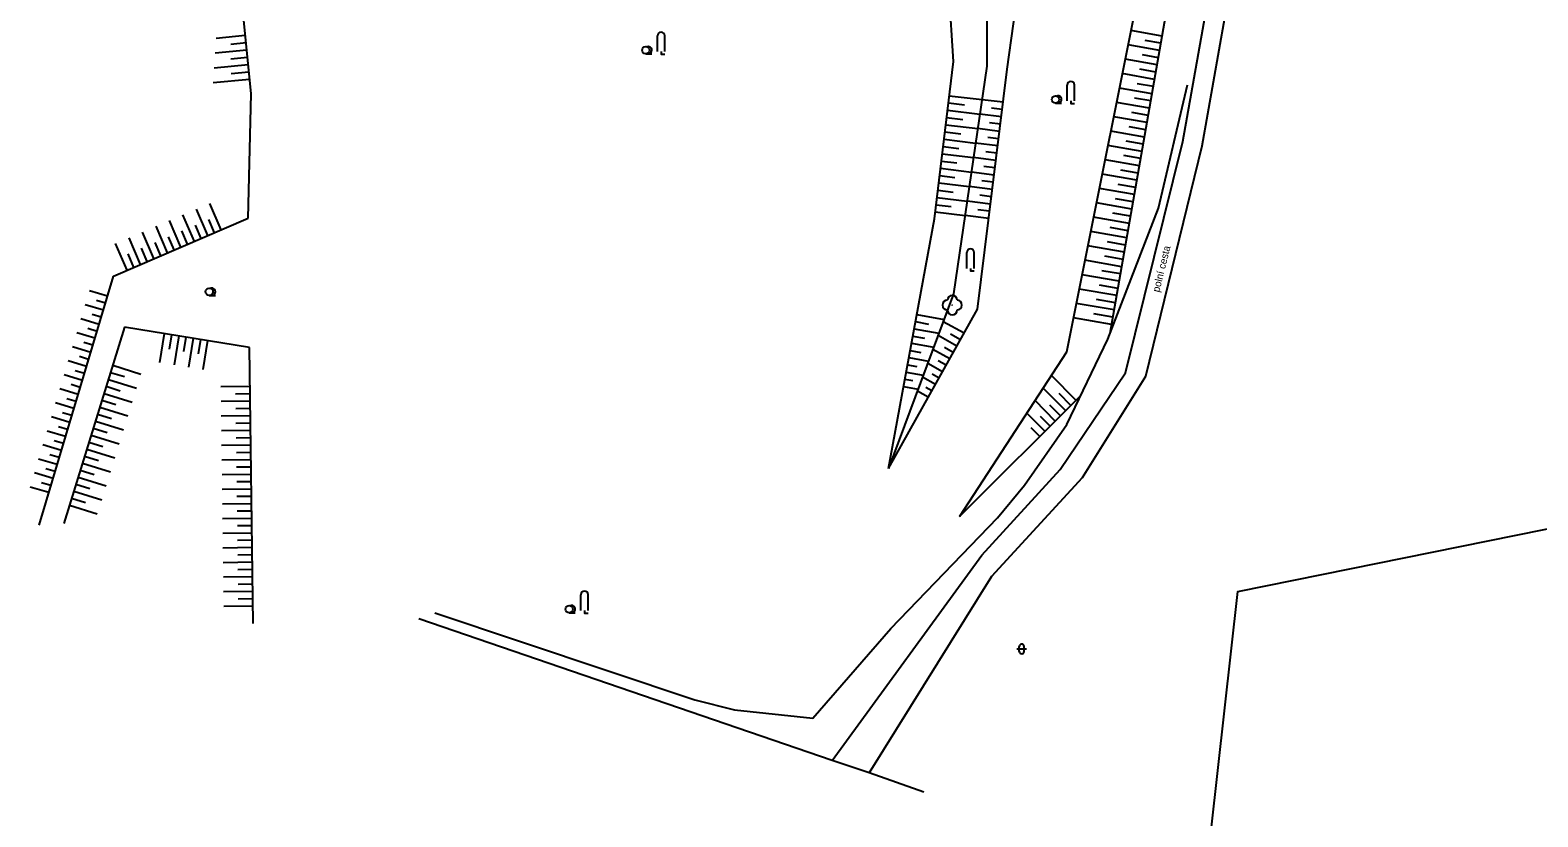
# Model space of a CAD drawing. Extents: x -737488 to -734267, y -1145775 to -1142573.
# Drawn here: x -735052.3 to -734897.8, y -1143083.7 to -1143003.1 of the extents above; entities that cross this region are included whole.
import ezdxf

# ---------------------------------------------------------------- set-up
doc = ezdxf.new("R2010")
doc.units = 0
for name, color, linetype in [('Vrstva 1', 7, 'Continuous'), ('Vrstva 10', 7, 'Continuous'), ('Vrstva 11', 7, 'Continuous'), ('Vrstva 12', 7, 'Continuous'), ('Vrstva 14', 7, 'Continuous'), ('Vrstva 3', 7, 'Continuous'), ('Vrstva 9', 7, 'Continuous')]:
    doc.layers.add(name, color=color, linetype=linetype)

# ---------------------------------------------------------------- blocks, each defined once
blk = doc.blocks.new('3.130')
at = {"layer": 'Vrstva 1'}
blk.add_circle((0, 0), 0.001, dxfattribs=at)
for centre, start, end in [((-1, 0), 90, 270), ((0, 1), 0, 180), ((1, 0), 270, 90), ((0, -1), 180, 360)]:
    blk.add_arc(centre, 1, start, end, dxfattribs=at)
blk = doc.blocks.new('3.100')
at = {"layer": 'Vrstva 1'}
for p, q in [((-0.75, 0), (-0.75, 3.25)), ((0.75, 0), (0.75, 3.25))]:
    blk.add_line(p, q, dxfattribs=at)
blk.add_lwpolyline([(0, 0), (0, -0.5), (0.75, -0.5)], dxfattribs=at)
blk.add_arc((0, 3.25), 0.75, 0, 180, dxfattribs=at)
blk = doc.blocks.new('3.110')
at = {"layer": 'Vrstva 1'}
blk.add_line((0, -0.75), (1.25, -0.75), dxfattribs=at)
blk.add_circle((0, 0), 0.75, dxfattribs=at)
blk.add_arc((0.5, 0), 0.75, 249.4944, 109.0474, dxfattribs=at)
blk = doc.blocks.new('3.160')
at = {"layer": 'Vrstva 1'}
for p, q in [((-1, 0), (1, 0)), ((-0.5, -0.5), (-0.5, 0.5)), ((0.5, -0.5), (0.5, 0.5))]:
    blk.add_line(p, q, dxfattribs=at)
for centre, start, end in [((0, 0.5), 0, 180), ((0, -0.5), 180, 360)]:
    blk.add_arc(centre, 0.5, start, end, dxfattribs=at)

msp = doc.modelspace()

# ---------------------------------------------------------------- linework, layer by layer
at = {"layer": 'Vrstva 10'}
for points in [[(-734934.2, -1143014.49), (-734928.93, -1142984.91)], [(-734927.04, -1142985.42), (-734932.25, -1143014.98)], [(-734940.09, -1143038.19), (-734934.2, -1143014.49)], [(-734932.25, -1143014.98), (-734938.02, -1143038.56)], [(-734946.76, -1143048.08), (-734940.09, -1143038.19)], [(-734938.02, -1143038.56), (-734944.5, -1143048.94)], [(-734954.79, -1143056.87), (-734946.76, -1143048.08)], [(-734944.5, -1143048.94), (-734953.81, -1143059.04)], [(-734970.13, -1143077.9), (-734954.79, -1143056.87)], [(-734953.81, -1143059.04), (-734966.34, -1143079.17)]]:
    msp.add_lwpolyline(points, dxfattribs=at)
at = {"layer": 'Vrstva 11'}
msp.add_lwpolyline([(-734932.65, -1143097.27), (-734928.56, -1143060.61), (-734817.4, -1143038.1), (-734801.73, -1143030.15)], dxfattribs=at)
at = {"layer": 'Vrstva 12'}
for points in [[(-734937.19, -1142991.51), (-734946.11, -1143036.08)], [(-734941.65, -1143034.14), (-734934.15, -1142991.37)], [(-734957.7, -1143006.28), (-734958.58, -1142992.32)], [(-734954.25, -1142992.81), (-734954.27, -1143006.77)], [(-734952.18, -1143007.07), (-734950.26, -1142993.11)], [(-735029.64, -1143009.61), (-735030.82, -1142997.59)], [(-735030.23, -1143003.64), (-735033.21, -1143003.93)], [(-735030.15, -1143004.39), (-735031.71, -1143004.54)], [(-734936.31, -1143003.68), (-734939.51, -1143003.12)], [(-734936.44, -1143004.42), (-734938.05, -1143004.14)], [(-735030.08, -1143005.13), (-735033.31, -1143005.45)], [(-735030.01, -1143005.88), (-735031.69, -1143006.04)], [(-734936.57, -1143005.16), (-734939.81, -1143004.59)], [(-734936.7, -1143005.9), (-734938.33, -1143005.61)], [(-735029.93, -1143006.62), (-735033.41, -1143006.97)], [(-735029.86, -1143007.37), (-735031.66, -1143007.55)], [(-734959.65, -1143022.42), (-734957.7, -1143006.28)], [(-734954.27, -1143006.77), (-734957.68, -1143030.1)], [(-734955.24, -1143031.68), (-734952.18, -1143007.07)], [(-734937.09, -1143008.12), (-734940.4, -1143007.53)], [(-734936.83, -1143006.64), (-734940.1, -1143006.06)], [(-734936.96, -1143007.38), (-734938.6, -1143007.09)], [(-735029.79, -1143008.12), (-735033.52, -1143008.48)], [(-734937.34, -1143009.59), (-734940.69, -1143009.01)], [(-734937.22, -1143008.85), (-734938.88, -1143008.56)], [(-735029.94, -1143022.35), (-735029.64, -1143009.61)], [(-734958.21, -1143010.53), (-734956.55, -1143010.73)], [(-734958.12, -1143009.79), (-734954.77, -1143010.19)], [(-734952.6, -1143010.47), (-734954.77, -1143010.2)], [(-734937.6, -1143011.07), (-734940.99, -1143010.48)], [(-734937.47, -1143010.33), (-734939.16, -1143010.04)], [(-734958.39, -1143012.02), (-734956.75, -1143012.22)], [(-734958.3, -1143011.28), (-734954.99, -1143011.68)], [(-734952.79, -1143011.96), (-734954.99, -1143011.69)], [(-734952.7, -1143011.22), (-734953.79, -1143011.08)], [(-734937.86, -1143012.55), (-734941.28, -1143011.95)], [(-734937.73, -1143011.81), (-734939.43, -1143011.51)], [(-734958.57, -1143013.51), (-734956.94, -1143013.71)], [(-734958.48, -1143012.77), (-734955.21, -1143013.16)], [(-734952.97, -1143013.45), (-734955.21, -1143013.17)], [(-734952.88, -1143012.71), (-734953.99, -1143012.57)], [(-734938.12, -1143014.03), (-734941.58, -1143013.42)], [(-734937.99, -1143013.29), (-734939.71, -1143012.99)], [(-734958.75, -1143015), (-734957.14, -1143015.19)], [(-734958.66, -1143014.26), (-734955.42, -1143014.65)], [(-734953.16, -1143014.94), (-734955.42, -1143014.66)], [(-734953.07, -1143014.2), (-734954.19, -1143014.06)], [(-734938.38, -1143015.5), (-734941.87, -1143014.89)], [(-734938.25, -1143014.76), (-734939.99, -1143014.46)], [(-734958.93, -1143016.49), (-734957.34, -1143016.68)], [(-734958.84, -1143015.74), (-734955.64, -1143016.13)], [(-734953.34, -1143016.43), (-734955.64, -1143016.14)], [(-734953.25, -1143015.68), (-734954.39, -1143015.54)], [(-734938.64, -1143016.98), (-734942.16, -1143016.36)], [(-734938.51, -1143016.24), (-734940.26, -1143015.93)], [(-734959.11, -1143017.98), (-734957.54, -1143018.17)], [(-734959.02, -1143017.23), (-734955.86, -1143017.62)], [(-734953.53, -1143017.92), (-734955.86, -1143017.63)], [(-734953.44, -1143017.17), (-734954.59, -1143017.03)], [(-734938.9, -1143018.46), (-734942.46, -1143017.83)], [(-734938.77, -1143017.72), (-734940.54, -1143017.41)], [(-734959.29, -1143019.47), (-734957.74, -1143019.66)], [(-734959.2, -1143018.72), (-734956.07, -1143019.1)], [(-734953.71, -1143019.41), (-734956.07, -1143019.11)], [(-734953.62, -1143018.66), (-734954.79, -1143018.52)], [(-734939.16, -1143019.93), (-734942.75, -1143019.3)], [(-734939.03, -1143019.2), (-734940.82, -1143018.88)], [(-735034.06, -1143024.12), (-735035.23, -1143021.42)], [(-735032.69, -1143023.53), (-735033.85, -1143020.83)], [(-734959.47, -1143020.96), (-734957.94, -1143021.14)], [(-734959.38, -1143020.21), (-734956.29, -1143020.59)], [(-734953.9, -1143020.89), (-734956.29, -1143020.6)], [(-734953.81, -1143020.15), (-734954.99, -1143020)], [(-734939.42, -1143021.41), (-734943.05, -1143020.78)], [(-734939.29, -1143020.67), (-734941.09, -1143020.36)], [(-735043.71, -1143028.27), (-735029.94, -1143022.35)], [(-735036.82, -1143025.31), (-735037.99, -1143022.59)], [(-735035.44, -1143024.72), (-735036.61, -1143022)], [(-735033.38, -1143023.83), (-735033.96, -1143022.47)], [(-734964.34, -1143047.98), (-734959.65, -1143022.42)], [(-734959.56, -1143021.7), (-734956.51, -1143022.07)], [(-734954.08, -1143022.38), (-734956.51, -1143022.08)], [(-734953.99, -1143021.64), (-734955.2, -1143021.49)], [(-734939.68, -1143022.89), (-734943.34, -1143022.25)], [(-734939.55, -1143022.15), (-734941.37, -1143021.83)], [(-735040.95, -1143027.09), (-735042.13, -1143024.34)], [(-735039.58, -1143026.49), (-735040.75, -1143023.76)], [(-735038.2, -1143025.9), (-735039.37, -1143023.17)], [(-735037.51, -1143025.6), (-735038.1, -1143024.24)], [(-735036.13, -1143025.01), (-735036.72, -1143023.65)], [(-735034.75, -1143024.42), (-735035.34, -1143023.06)], [(-734939.93, -1143024.37), (-734943.64, -1143023.72)], [(-734939.81, -1143023.63), (-734941.65, -1143023.31)], [(-735042.33, -1143027.68), (-735043.51, -1143024.93)], [(-735041.64, -1143027.38), (-735042.23, -1143026.01)], [(-735040.27, -1143026.79), (-735040.85, -1143025.42)], [(-735038.89, -1143026.2), (-735039.47, -1143024.83)], [(-734940.19, -1143025.84), (-734943.93, -1143025.19)], [(-734940.06, -1143025.11), (-734941.92, -1143024.78)], [(-734940.45, -1143027.32), (-734944.23, -1143026.66)], [(-734940.32, -1143026.58), (-734942.2, -1143026.25)], [(-735051.35, -1143053.79), (-735043.71, -1143028.27)], [(-734940.71, -1143028.8), (-734944.52, -1143028.13)], [(-734940.58, -1143028.06), (-734942.48, -1143027.73)], [(-735044.33, -1143030.34), (-735046.19, -1143029.79)], [(-734957.68, -1143030.1), (-734964.34, -1143047.98)], [(-734940.97, -1143030.28), (-734944.81, -1143029.6)], [(-734941.1, -1143031.02), (-734943.03, -1143030.68)], [(-734940.84, -1143029.54), (-734942.75, -1143029.2)], [(-735044.76, -1143031.78), (-735046.62, -1143031.22)], [(-735044.98, -1143032.5), (-735045.91, -1143032.22)], [(-735044.55, -1143031.06), (-735045.48, -1143030.78)], [(-734964.34, -1143047.98), (-734955.24, -1143031.68)], [(-734961.45, -1143032.21), (-734958.66, -1143032.72)], [(-734941.23, -1143031.75), (-734945.11, -1143031.07)], [(-734941.36, -1143032.49), (-734943.31, -1143032.15)], [(-735042.58, -1143033.5), (-735048.82, -1143053.61)], [(-735045.19, -1143033.22), (-735047.06, -1143032.66)], [(-735045.41, -1143033.94), (-735046.34, -1143033.66)], [(-735029.78, -1143035.58), (-735042.58, -1143033.5)], [(-734961.72, -1143033.68), (-734959.19, -1143034.14)], [(-734961.58, -1143032.94), (-734960.25, -1143033.19)], [(-734956.61, -1143034.14), (-734958.74, -1143032.95)], [(-734941.49, -1143033.23), (-734945.4, -1143032.55)], [(-735045.62, -1143034.65), (-735047.49, -1143034.1)], [(-735045.84, -1143035.37), (-735046.77, -1143035.09)], [(-735038.52, -1143034.16), (-735039, -1143037.12)], [(-735037.78, -1143034.28), (-735038.02, -1143035.76)], [(-735037.04, -1143034.4), (-735037.52, -1143037.36)], [(-735036.3, -1143034.52), (-735036.54, -1143036)], [(-735035.56, -1143034.64), (-735036.04, -1143037.6)], [(-735034.82, -1143034.76), (-735035.06, -1143036.24)], [(-735034.08, -1143034.88), (-735034.56, -1143037.84)], [(-734961.99, -1143035.16), (-734959.72, -1143035.57)], [(-734961.85, -1143034.42), (-734960.65, -1143034.64)], [(-734957.35, -1143035.45), (-734959.27, -1143034.37)], [(-734956.98, -1143034.8), (-734957.99, -1143034.23)], [(-735046.05, -1143036.09), (-735047.92, -1143035.53)], [(-735046.27, -1143036.81), (-735047.2, -1143036.53)], [(-735029.41, -1143063.86), (-735029.78, -1143035.58)], [(-734962.26, -1143036.63), (-734960.25, -1143037)], [(-734962.12, -1143035.89), (-734961.05, -1143036.09)], [(-734958.08, -1143036.76), (-734959.8, -1143035.8)], [(-734957.71, -1143036.11), (-734958.62, -1143035.6)], [(-734946.11, -1143036.08), (-734957.08, -1143052.91)], [(-735046.91, -1143038.97), (-735048.79, -1143038.4)], [(-735046.48, -1143037.53), (-735048.36, -1143036.97)], [(-735046.7, -1143038.25), (-735047.64, -1143037.97)], [(-735044.02, -1143038.14), (-735042.59, -1143038.58)], [(-735043.8, -1143037.42), (-735040.93, -1143038.31)], [(-734962.53, -1143038.11), (-734960.78, -1143038.43)], [(-734962.39, -1143037.37), (-734961.46, -1143037.54)], [(-734958.81, -1143038.07), (-734960.33, -1143037.22)], [(-734959.17, -1143038.73), (-734959.88, -1143038.33)], [(-734958.44, -1143037.42), (-734959.25, -1143036.96)], [(-735047.34, -1143040.4), (-735049.23, -1143039.84)], [(-735047.13, -1143039.68), (-735048.07, -1143039.4)], [(-735044.46, -1143039.57), (-735043.03, -1143040.02)], [(-735044.24, -1143038.86), (-735041.37, -1143039.75)], [(-735029.73, -1143039.6), (-735032.73, -1143039.64)], [(-734962.8, -1143039.58), (-734961.31, -1143039.85)], [(-734962.66, -1143038.84), (-734961.86, -1143038.99)], [(-734959.54, -1143039.38), (-734960.86, -1143038.64)], [(-734959.9, -1143040.03), (-734960.52, -1143039.69)], [(-734946.19, -1143042.07), (-734948.5, -1143039.75)], [(-734945.13, -1143041.01), (-734947.66, -1143038.46)], [(-735047.77, -1143041.84), (-735049.66, -1143041.27)], [(-735047.56, -1143041.12), (-735048.5, -1143040.84)], [(-735044.91, -1143041), (-735043.48, -1143041.45)], [(-735044.69, -1143040.29), (-735041.82, -1143041.18)], [(-735029.71, -1143041.1), (-735032.71, -1143041.14)], [(-735029.72, -1143040.35), (-735031.22, -1143040.37)], [(-734960.27, -1143040.69), (-734961.39, -1143040.06)], [(-734957.08, -1143052.91), (-734944.68, -1143040.56)], [(-734947.26, -1143043.13), (-734949.34, -1143041.03)], [(-734946.72, -1143042.6), (-734947.82, -1143041.49)], [(-734945.66, -1143041.54), (-734946.87, -1143040.32)], [(-735048.2, -1143043.28), (-735050.09, -1143042.71)], [(-735047.99, -1143042.56), (-735048.93, -1143042.28)], [(-735045.35, -1143042.44), (-735043.92, -1143042.88)], [(-735045.13, -1143041.72), (-735042.26, -1143042.61)], [(-735029.69, -1143042.6), (-735032.69, -1143042.64)], [(-735029.7, -1143041.85), (-735031.2, -1143041.87)], [(-734948.32, -1143044.18), (-734950.18, -1143042.32)], [(-734947.79, -1143043.66), (-734948.77, -1143042.67)], [(-735048.63, -1143044.71), (-735050.53, -1143044.15)], [(-735048.42, -1143044), (-735049.36, -1143043.71)], [(-735046.02, -1143044.59), (-735043.15, -1143045.48)], [(-735045.8, -1143043.87), (-735044.36, -1143044.31)], [(-735045.58, -1143043.15), (-735042.71, -1143044.04)], [(-735029.67, -1143044.1), (-735032.67, -1143044.14)], [(-735029.68, -1143043.35), (-735031.18, -1143043.37)], [(-734948.85, -1143044.71), (-734949.72, -1143043.84)], [(-735049.06, -1143046.15), (-735050.96, -1143045.58)], [(-735048.85, -1143045.43), (-735049.8, -1143045.15)], [(-735046.47, -1143046.02), (-735043.6, -1143046.91)], [(-735046.24, -1143045.3), (-735044.81, -1143045.75)], [(-735029.65, -1143045.6), (-735032.65, -1143045.64)], [(-735029.66, -1143044.85), (-735031.16, -1143044.87)], [(-735049.49, -1143047.59), (-735051.4, -1143047.02)], [(-735049.28, -1143046.87), (-735050.23, -1143046.58)], [(-735046.91, -1143047.45), (-735044.04, -1143048.34)], [(-735046.69, -1143046.74), (-735045.25, -1143047.18)], [(-735029.63, -1143047.1), (-735032.63, -1143047.14)], [(-735029.64, -1143046.35), (-735031.14, -1143046.37)], [(-735049.92, -1143049.02), (-735051.83, -1143048.45)], [(-735049.71, -1143048.31), (-735050.66, -1143048.02)], [(-735047.35, -1143048.88), (-735044.49, -1143049.77)], [(-735047.13, -1143048.17), (-735045.7, -1143048.61)], [(-735029.61, -1143048.6), (-735032.61, -1143048.64)], [(-735029.62, -1143047.85), (-735031.12, -1143047.87)], [(-735050.35, -1143050.46), (-735052.26, -1143049.89)], [(-735050.14, -1143049.74), (-735051.09, -1143049.46)], [(-735047.8, -1143050.32), (-735044.93, -1143051.21)], [(-735047.58, -1143049.6), (-735046.14, -1143050.05)], [(-735029.59, -1143050.1), (-735032.59, -1143050.14)], [(-735029.6, -1143049.35), (-735031.1, -1143049.37)], [(-735048.24, -1143051.75), (-735045.38, -1143052.64)], [(-735048.02, -1143051.03), (-735046.59, -1143051.48)], [(-735029.57, -1143051.6), (-735032.57, -1143051.64)], [(-735029.58, -1143050.85), (-735031.08, -1143050.87)], [(-735029.56, -1143052.35), (-735031.06, -1143052.37)], [(-735029.55, -1143053.1), (-735032.55, -1143053.14)], [(-735029.54, -1143053.85), (-735031.04, -1143053.87)], [(-735029.53, -1143054.6), (-735032.53, -1143054.64)], [(-735029.52, -1143055.35), (-735031.02, -1143055.37)], [(-735029.51, -1143056.1), (-735032.51, -1143056.14)], [(-735029.5, -1143056.85), (-735031, -1143056.87)], [(-735029.49, -1143057.6), (-735032.49, -1143057.64)], [(-735029.48, -1143058.35), (-735030.98, -1143058.37)], [(-735029.47, -1143059.1), (-735032.47, -1143059.14)], [(-735029.46, -1143059.85), (-735030.96, -1143059.87)], [(-735029.45, -1143060.6), (-735032.45, -1143060.64)], [(-735029.44, -1143061.35), (-735030.94, -1143061.37)], [(-735029.43, -1143062.1), (-735032.44, -1143062.14)]]:
    msp.add_lwpolyline(points, dxfattribs=at)
at = {"layer": 'Vrstva 9'}
for points in [[(-735010.8, -1143062.79), (-734984.18, -1143071.68), (-734980.11, -1143072.72), (-734972.11, -1143073.57), (-734964.1, -1143064.38), (-734953.17, -1143053.05), (-734950.43, -1143049.7), (-734946.08, -1143043.47), (-734941.88, -1143034.74), (-734936.69, -1143021.33), (-734933.74, -1143008.68)], [(-734970.13, -1143077.9), (-735012.44, -1143063.41)], [(-734966.34, -1143079.17), (-734970.13, -1143077.9)], [(-734960.72, -1143081.17), (-734966.34, -1143079.17)]]:
    msp.add_lwpolyline(points, dxfattribs=at)

# ---------------------------------------------------------------- block references
at = {"layer": 'Vrstva 11', "xscale": 0.5, "yscale": 0.5}
msp.add_blockref('3.130', (-734957.82, -1143031.25), dxfattribs=at)
at = {"layer": 'Vrstva 3', "xscale": 0.5, "yscale": 0.5}
for name, p in [('3.100', (-734987.64, -1143005.28)), ('3.110', (-734989.21, -1143005.13)), ('3.100', (-734945.68, -1143010.33)), ('3.110', (-734947.25, -1143010.18)), ('3.100', (-734955.95, -1143027.49)), ('3.110', (-735033.91, -1143029.88)), ('3.100', (-734995.48, -1143062.55)), ('3.110', (-734997.05, -1143062.4)), ('3.160', (-734950.7, -1143066.48))]:
    msp.add_blockref(name, p, dxfattribs=at)

# ---------------------------------------------------------------- texts
at = {"layer": 'Vrstva 14'}
msp.add_text('polní cesta', height=0.75, rotation=76.25, dxfattribs=at).set_placement((-734936.61, -1143029.98))

doc.saveas('drawing.dxf')
